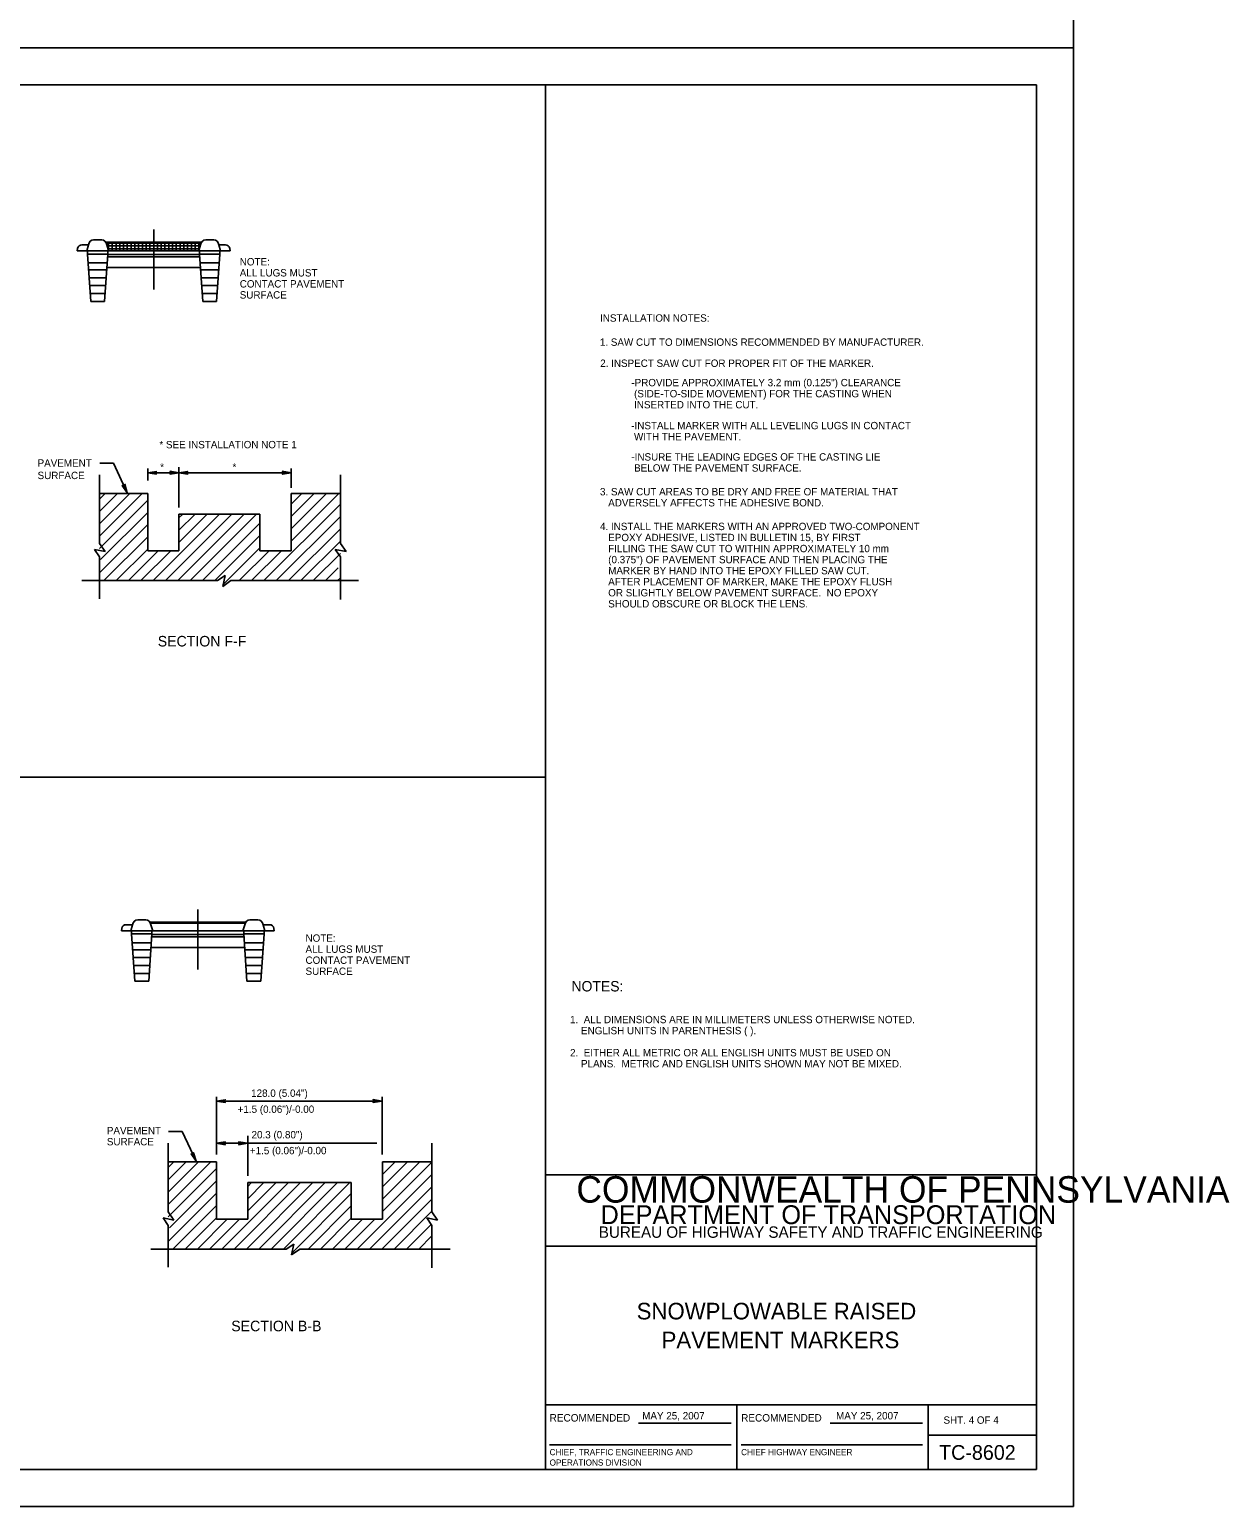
# Model space of a CAD drawing. Extents: x 639362 to 641108, y 298458 to 299646.
# Drawn here: x 640619 to 641108, y 298458 to 299059 of the extents above; entities that cross this region are included whole.
import ezdxf

# ---------------------------------------------------------------- set-up
doc = ezdxf.new("R2010")
doc.units = 0
for name, color, linetype in [('1', 7, 'Continuous'), ('2', 7, 'Continuous'), ('PLT-BNDY', 7, 'Continuous')]:
    doc.layers.add(name, color=color, linetype=linetype)

msp = doc.modelspace()

# ---------------------------------------------------------------- linework, layer by layer
at = {"layer": '1'}
for p, q in [((640243.31, 299036.63), (641029.31, 299036.63)), ((640829.31, 298592.63), (640829.31, 299036.63)), ((641029.31, 298472.63), (641029.31, 299036.63)), ((640243.31, 298754.63), (640829.31, 298754.63)), ((640829.31, 298472.63), (640829.31, 298592.63)), ((640829.31, 298592.63), (641029.31, 298592.63)), ((641029.31, 298563.63), (640829.31, 298563.63)), ((640829.31, 298499), (641029.31, 298499)), ((640907.31, 298499), (640907.31, 298472.63)), ((640985.19, 298472.63), (640985.19, 298499)), ((640867.24, 298491.57), (640904.87, 298491.57)), ((640945.24, 298491.57), (640982.87, 298491.57)), ((640830.99, 298482.68), (640904.87, 298482.68)), ((640908.99, 298482.68), (640982.87, 298482.68)), ((640985.19, 298486.63), (641029.31, 298486.63)), ((641029.31, 298472.63), (640243.31, 298472.63)), ((640243.31, 298472.63), (640829.31, 298472.63))]:
    msp.add_line(p, q, dxfattribs=at)
at = {"layer": '2'}
for p, q in [((640669.77, 298977.68), (640669.77, 298953.22)), ((640638.64, 298969.01), (640638.78, 298969.98)), ((640643.2, 298971.48), (640640.53, 298971.48)), ((640642.5, 298969.01), (640643.19, 298971.43)), ((640645.29, 298973.5), (640648.59, 298973.5)), ((640650.27, 298972.5), (640689.27, 298972.5)), ((640650.48, 298972.11), (640689.08, 298972.11)), ((640651.38, 298969.01), (640650.68, 298971.43)), ((640651.07, 298971.07), (640688.46, 298971.07)), ((640651.07, 298969.88), (640688.46, 298969.88)), ((640651.36, 298972.11), (640651.36, 298969.01)), ((640652.9, 298972.11), (640652.9, 298969.01)), ((640654.43, 298972.11), (640654.43, 298969.01)), ((640655.96, 298972.11), (640655.96, 298969.01)), ((640657.5, 298972.11), (640657.5, 298969.01)), ((640659.03, 298972.11), (640659.03, 298969.01)), ((640660.56, 298972.11), (640660.56, 298969.01)), ((640662.1, 298972.11), (640662.1, 298969.01)), ((640663.63, 298972.11), (640663.63, 298969.01)), ((640665.17, 298972.11), (640665.17, 298969.01)), ((640666.7, 298972.11), (640666.7, 298969.01)), ((640668.23, 298972.11), (640668.23, 298969.01)), ((640669.77, 298972.11), (640669.77, 298969.01)), ((640671.3, 298972.11), (640671.3, 298969.01)), ((640672.83, 298972.11), (640672.83, 298969.01)), ((640674.36, 298972.11), (640674.36, 298969.01)), ((640675.9, 298972.11), (640675.9, 298969.01)), ((640677.43, 298972.11), (640677.43, 298969.01)), ((640678.97, 298972.11), (640678.97, 298969.01)), ((640680.5, 298972.11), (640680.5, 298969.01)), ((640682.03, 298972.11), (640682.03, 298969.01)), ((640683.57, 298972.11), (640683.57, 298969.01)), ((640685.1, 298972.11), (640685.1, 298969.01)), ((640686.63, 298972.11), (640686.63, 298969.01)), ((640688.15, 298969.01), (640688.85, 298971.43)), ((640688.17, 298972.11), (640688.17, 298969.01)), ((640694.24, 298973.5), (640690.94, 298973.5)), ((640696.33, 298971.48), (640699, 298971.48)), ((640697.03, 298969.01), (640696.33, 298971.43)), ((640700.89, 298969.01), (640700.75, 298969.98)), ((640642.75, 298969.01), (640638.64, 298969.01)), ((640642.5, 298969.01), (640651.38, 298969.01)), ((640642.79, 298967.68), (640642.79, 298969.01)), ((640644.12, 298948.4), (640642.79, 298967.68)), ((640642.79, 298967.68), (640651.09, 298967.68)), ((640650.84, 298964.12), (640643.03, 298964.12)), ((640649.77, 298948.4), (640651.09, 298967.68)), ((640651.01, 298966.54), (640688.52, 298966.54)), ((640651.07, 298967.46), (640688.46, 298967.46)), ((640651.09, 298967.68), (640651.09, 298969.01)), ((640651.13, 298969.01), (640688.4, 298969.01)), ((640688.15, 298969.01), (640697.03, 298969.01)), ((640688.44, 298967.68), (640688.44, 298969.01)), ((640689.77, 298948.4), (640688.44, 298967.68)), ((640688.44, 298967.68), (640696.74, 298967.68)), ((640688.68, 298964.12), (640696.5, 298964.12)), ((640695.41, 298948.4), (640696.74, 298967.68)), ((640696.74, 298967.68), (640696.74, 298969.01)), ((640696.78, 298969.01), (640700.89, 298969.01)), ((640650.65, 298961.26), (640643.23, 298961.26)), ((640650.43, 298958.05), (640643.45, 298958.05)), ((640650.71, 298962.2), (640688.82, 298962.2)), ((640688.88, 298961.26), (640696.3, 298961.26)), ((640689.1, 298958.05), (640696.08, 298958.05)), ((640650.21, 298954.83), (640643.68, 298954.83)), ((640649.99, 298951.62), (640643.9, 298951.62)), ((640689.32, 298954.83), (640695.85, 298954.83)), ((640689.54, 298951.62), (640695.63, 298951.62)), ((640649.77, 298948.4), (640644.12, 298948.4)), ((640689.77, 298948.4), (640695.41, 298948.4)), ((640647.82, 298882.56), (640653.38, 298882.56)), ((640653.38, 298882.56), (640659, 298870.44)), ((640667.32, 298880.4), (640667.32, 298875.51)), ((640680.07, 298880.95), (640680.07, 298864.44)), ((640725.71, 298880.4), (640725.71, 298872.49)), ((640647.65, 298877.84), (640647.65, 298849.8)), ((640667.32, 298878.62), (640725.71, 298878.62)), ((640745.78, 298877.84), (640745.78, 298849.8)), ((640667.32, 298870.23), (640647.65, 298870.23)), ((640647.65, 298867.87), (640650.01, 298870.23)), ((640647.65, 298862.86), (640655.02, 298870.23)), ((640647.65, 298857.85), (640660.03, 298870.23)), ((640647.65, 298852.84), (640665.04, 298870.23)), ((640647.65, 298847.83), (640667.32, 298867.5)), ((640667.32, 298870.23), (640667.32, 298846.76)), ((640725.71, 298870.23), (640725.71, 298846.86)), ((640725.71, 298870.23), (640745.78, 298870.23)), ((640725.71, 298865.79), (640730.15, 298870.23)), ((640725.71, 298860.78), (640735.16, 298870.23)), ((640725.71, 298855.77), (640740.17, 298870.23)), ((640725.71, 298850.77), (640745.18, 298870.23)), ((640648.15, 298843.33), (640667.32, 298862.49)), ((640669.56, 298834.68), (640696.61, 298861.73)), ((640674.56, 298834.68), (640701.62, 298861.73)), ((640679.57, 298834.68), (640706.63, 298861.73)), ((640680.07, 298861.73), (640680.07, 298846.86)), ((640712.96, 298861.73), (640680.07, 298861.73)), ((640680.07, 298860.22), (640681.58, 298861.73)), ((640680.07, 298855.21), (640686.59, 298861.73)), ((640680.07, 298850.2), (640691.6, 298861.73)), ((640684.58, 298834.68), (640711.63, 298861.73)), ((640712.96, 298861.73), (640712.96, 298846.76)), ((640714.63, 298834.68), (640745.78, 298865.82)), ((640647.65, 298837.81), (640667.32, 298857.48)), ((640689.59, 298834.68), (640712.96, 298858.05)), ((640719.64, 298834.68), (640745.78, 298860.81)), ((640724.65, 298834.68), (640745.78, 298855.81)), ((640650, 298846.51), (640647.65, 298849.8)), ((640649.52, 298834.68), (640667.32, 298852.47)), ((640694.6, 298834.68), (640712.96, 298853.04)), ((640729.66, 298834.68), (640745.78, 298850.8)), ((640748.13, 298846.51), (640745.78, 298849.8)), ((640647.65, 298844.33), (640645.6, 298847.41)), ((640645.6, 298847.41), (640650, 298846.51)), ((640647.65, 298844.33), (640647.65, 298827.29)), ((640654.53, 298834.68), (640667.32, 298847.47)), ((640659.54, 298834.68), (640671.65, 298846.79)), ((640664.55, 298834.68), (640676.7, 298846.83)), ((640667.32, 298846.86), (640680.07, 298846.86)), ((640698.1, 298833.17), (640712.96, 298848.03)), ((640704.62, 298834.68), (640716.8, 298846.86)), ((640709.62, 298834.68), (640721.8, 298846.86)), ((640712.96, 298846.86), (640725.71, 298846.86)), ((640734.67, 298834.68), (640745.78, 298845.79)), ((640745.78, 298844.33), (640743.73, 298847.41)), ((640743.73, 298847.41), (640748.13, 298846.51)), ((640745.78, 298844.33), (640745.78, 298827.06)), ((640739.68, 298834.68), (640744.9, 298839.89)), ((640695.75, 298834.68), (640640.55, 298834.68)), ((640695.75, 298834.68), (640698.83, 298836.73)), ((640698.83, 298836.73), (640697.93, 298832.33)), ((640697.93, 298832.33), (640701.22, 298834.68)), ((640753.23, 298834.68), (640701.22, 298834.68)), ((640744.68, 298834.68), (640745.78, 298835.77)), ((640687.74, 298700.77), (640687.74, 298676.31)), ((640656.61, 298692.1), (640656.76, 298693.07)), ((640661.18, 298694.57), (640658.51, 298694.57)), ((640660.47, 298692.1), (640661.17, 298694.53)), ((640663.27, 298696.59), (640666.56, 298696.59)), ((640668.24, 298695.6), (640707.24, 298695.6)), ((640668.46, 298695.2), (640707.06, 298695.2)), ((640669.35, 298692.1), (640668.66, 298694.53)), ((640706.13, 298692.1), (640706.82, 298694.53)), ((640712.21, 298696.59), (640708.92, 298696.59)), ((640714.3, 298694.57), (640716.97, 298694.57)), ((640715, 298692.1), (640714.31, 298694.53)), ((640718.87, 298692.1), (640718.72, 298693.07)), ((640660.72, 298692.1), (640656.61, 298692.1)), ((640660.47, 298692.1), (640669.35, 298692.1)), ((640660.76, 298690.78), (640660.76, 298692.1)), ((640662.09, 298671.5), (640660.76, 298690.78)), ((640660.76, 298690.78), (640669.06, 298690.78)), ((640668.82, 298687.21), (640661.01, 298687.21)), ((640667.74, 298671.5), (640669.06, 298690.78)), ((640668.98, 298689.63), (640706.49, 298689.63)), ((640669.05, 298690.55), (640706.43, 298690.55)), ((640669.06, 298690.78), (640669.06, 298692.1)), ((640669.1, 298692.1), (640706.37, 298692.1)), ((640706.13, 298692.1), (640715, 298692.1)), ((640706.41, 298690.78), (640706.41, 298692.1)), ((640707.74, 298671.5), (640706.41, 298690.78)), ((640706.41, 298690.78), (640714.72, 298690.78)), ((640706.66, 298687.21), (640714.47, 298687.21)), ((640713.38, 298671.5), (640714.72, 298690.78)), ((640714.72, 298690.78), (640714.72, 298692.1)), ((640714.76, 298692.1), (640718.87, 298692.1)), ((640668.62, 298684.35), (640661.2, 298684.35)), ((640668.4, 298681.14), (640661.43, 298681.14)), ((640668.69, 298685.3), (640706.79, 298685.3)), ((640706.85, 298684.35), (640714.27, 298684.35)), ((640707.08, 298681.14), (640714.05, 298681.14)), ((640668.18, 298677.93), (640661.65, 298677.93)), ((640707.3, 298677.93), (640713.83, 298677.93)), ((640667.96, 298674.71), (640661.87, 298674.71)), ((640667.74, 298671.5), (640662.09, 298671.5)), ((640707.52, 298674.71), (640713.6, 298674.71)), ((640707.74, 298671.5), (640713.38, 298671.5)), ((640695.32, 298624.5), (640695.32, 298601)), ((640695.32, 298622.72), (640762.65, 298622.72)), ((640762.82, 298624.5), (640762.82, 298601)), ((640675.82, 298610.34), (640681.38, 298610.34)), ((640681.38, 298610.34), (640687.01, 298598.21)), ((640675.65, 298605.61), (640675.65, 298577.57)), ((640695.32, 298605.54), (640760.58, 298605.54)), ((640708.07, 298608.54), (640708.07, 298592.22)), ((640783.03, 298605.61), (640783.03, 298577.57)), ((640695.32, 298598), (640675.65, 298598)), ((640675.65, 298595.64), (640678.02, 298598)), ((640675.65, 298590.63), (640683.03, 298598)), ((640675.65, 298585.62), (640688.04, 298598)), ((640675.65, 298580.61), (640693.04, 298598)), ((640695.32, 298598), (640695.32, 298574.53)), ((640762.96, 298598), (640762.96, 298574.63)), ((640762.96, 298598), (640783.03, 298598)), ((640762.96, 298582.78), (640778.19, 298598)), ((640762.96, 298587.78), (640773.18, 298598)), ((640762.96, 298592.79), (640768.17, 298598)), ((640762.96, 298577.77), (640783.03, 298597.84)), ((640675.65, 298575.6), (640695.32, 298595.27)), ((640752.65, 298562.45), (640783.03, 298592.83)), ((640675.65, 298565.59), (640695.32, 298585.26)), ((640676.16, 298571.1), (640695.32, 298590.27)), ((640697.56, 298562.45), (640724.61, 298589.5)), ((640702.57, 298562.45), (640729.62, 298589.5)), ((640707.58, 298562.45), (640734.63, 298589.5)), ((640708.07, 298589.5), (640708.07, 298574.63)), ((640750.21, 298589.5), (640708.07, 298589.5)), ((640708.07, 298587.99), (640709.59, 298589.5)), ((640708.07, 298582.98), (640714.6, 298589.5)), ((640708.07, 298577.97), (640719.6, 298589.5)), ((640712.59, 298562.45), (640739.64, 298589.5)), ((640717.59, 298562.45), (640744.65, 298589.5)), ((640722.6, 298562.45), (640749.66, 298589.5)), ((640726.11, 298560.95), (640750.21, 298585.05)), ((640750.21, 298589.5), (640750.21, 298574.53)), ((640757.66, 298562.45), (640783.03, 298587.82)), ((640677.53, 298562.45), (640695.32, 298580.25)), ((640732.62, 298562.45), (640750.21, 298580.04)), ((640762.67, 298562.45), (640783.03, 298582.81)), ((640675.65, 298572.11), (640673.6, 298575.19)), ((640673.6, 298575.19), (640678, 298574.28)), ((640678, 298574.28), (640675.65, 298577.57)), ((640682.53, 298562.45), (640695.32, 298575.24)), ((640687.54, 298562.45), (640699.66, 298574.57)), ((640692.55, 298562.45), (640704.7, 298574.6)), ((640695.32, 298574.63), (640708.07, 298574.63)), ((640737.63, 298562.45), (640750.21, 298575.03)), ((640742.64, 298562.45), (640754.82, 298574.63)), ((640747.64, 298562.45), (640759.82, 298574.63)), ((640750.21, 298574.63), (640762.96, 298574.63)), ((640767.68, 298562.45), (640782.93, 298577.71)), ((640783.03, 298572.11), (640780.98, 298575.19)), ((640780.98, 298575.19), (640785.38, 298574.28)), ((640785.38, 298574.28), (640783.03, 298577.57)), ((640675.65, 298572.11), (640675.65, 298555.07)), ((640772.69, 298562.45), (640782.75, 298572.52)), ((640777.7, 298562.45), (640783.03, 298567.78)), ((640783.03, 298572.11), (640783.03, 298554.84)), ((640723.76, 298562.45), (640668.55, 298562.45)), ((640723.76, 298562.45), (640726.84, 298564.5)), ((640726.84, 298564.5), (640725.93, 298560.1)), ((640725.93, 298560.1), (640729.22, 298562.45)), ((640790.48, 298562.45), (640729.22, 298562.45))]:
    msp.add_line(p, q, dxfattribs=at)
for points in [[(640657.96, 298873.71), (640657.79, 298873.49), (640659, 298870.44), (640657.96, 298873.71), (640658.02, 298873.93), (640659, 298870.44), (640657.48, 298873.34), (640657.21, 298873.35), (640659, 298870.44), (640656.98, 298873.45), (640657.21, 298873.35)], [(640670.72, 298878.2), (640670.6, 298878.44), (640667.32, 298878.62), (640670.72, 298878.2), (640670.9, 298878.05), (640667.32, 298878.62), (640670.59, 298878.79), (640670.71, 298879.03), (640667.32, 298878.62), (640670.9, 298879.19), (640670.71, 298879.03)], [(640676.59, 298879.05), (640676.71, 298878.8), (640679.99, 298878.62), (640676.59, 298879.05), (640676.42, 298879.2), (640679.99, 298878.62), (640676.72, 298878.46), (640676.6, 298878.22), (640679.99, 298878.62), (640676.42, 298878.05), (640676.6, 298878.22)], [(640683.47, 298878.2), (640683.35, 298878.44), (640680.07, 298878.62), (640683.47, 298878.2), (640683.65, 298878.04), (640680.07, 298878.62), (640683.34, 298878.79), (640683.46, 298879.03), (640680.07, 298878.62), (640683.65, 298879.19), (640683.46, 298879.03)], [(640722.31, 298879.05), (640722.43, 298878.8), (640725.71, 298878.62), (640722.31, 298879.05), (640722.13, 298879.2), (640725.71, 298878.62), (640722.44, 298878.46), (640722.32, 298878.22), (640725.71, 298878.62), (640722.13, 298878.05), (640722.32, 298878.22)], [(640698.73, 298622.3), (640698.6, 298622.54), (640695.32, 298622.72), (640698.73, 298622.3), (640698.9, 298622.15), (640695.32, 298622.72), (640698.6, 298622.89), (640698.72, 298623.13), (640695.32, 298622.72), (640698.9, 298623.29), (640698.72, 298623.13)], [(640759.25, 298623.15), (640759.38, 298622.9), (640762.65, 298622.72), (640759.25, 298623.15), (640759.08, 298623.3), (640762.65, 298622.72), (640759.38, 298622.56), (640759.26, 298622.32), (640762.65, 298622.72), (640759.08, 298622.15), (640759.26, 298622.32)], [(640698.73, 298605.11), (640698.6, 298605.36), (640695.32, 298605.54), (640698.73, 298605.11), (640698.9, 298604.96), (640695.32, 298605.54), (640698.6, 298605.7), (640698.72, 298605.94), (640695.32, 298605.54), (640698.9, 298606.11), (640698.72, 298605.94)], [(640704.59, 298605.96), (640704.72, 298605.72), (640708, 298605.53), (640704.59, 298605.96), (640704.42, 298606.11), (640708, 298605.53), (640704.73, 298605.37), (640704.6, 298605.13), (640708, 298605.53), (640704.42, 298604.97), (640704.6, 298605.13)], [(640685.96, 298601.48), (640685.79, 298601.26), (640687.01, 298598.21), (640685.96, 298601.48), (640686.03, 298601.7), (640687.01, 298598.21), (640685.48, 298601.12), (640685.21, 298601.12), (640687.01, 298598.21), (640684.99, 298601.22), (640685.21, 298601.12)]]:
    msp.add_lwpolyline(points, dxfattribs=at)
for centre, start, end in [((640640.53, 298969.71), 90, 171.21944), ((640698.99, 298969.71), 8.78056, 90), ((640658.51, 298692.8), 90, 171.21944), ((640716.97, 298692.8), 8.78056, 90)]:
    msp.add_arc(centre, 1.77, start, end, dxfattribs=at)
for centre, start_param, end_param in [((640645.29, 298970.84), 0, 1.34621), ((640648.58, 298970.84), 4.937133, 6.283185), ((640690.94, 298970.84), 0, 1.346052), ((640694.24, 298970.84), 4.936975, 6.283185), ((640663.27, 298693.94), 0, 1.34621), ((640666.56, 298693.94), 4.937133, 6.283185), ((640708.92, 298693.94), 0, 1.346052), ((640712.21, 298693.94), 4.936975, 6.283185)]:
    msp.add_ellipse(centre, major_axis=(0, 2.66), ratio=0.81, start_param=start_param, end_param=end_param, dxfattribs=at)
at = {"layer": 'PLT-BNDY'}
for points in [[(640203.31, 299645.63), (641044.31, 299645.63), (641044.31, 299051.63), (640203.31, 299051.63)], [(640203.31, 299051.63), (641044.31, 299051.63), (641044.31, 298457.63), (640203.31, 298457.63)]]:
    msp.add_lwpolyline(points, close=True, dxfattribs=at)

# ---------------------------------------------------------------- texts
at = {"layer": '1'}
for s, height, p in [('COMMONWEALTH OF PENNSYLVANIA', 10.7828, (640841.9, 298581.36)), ('DEPARTMENT OF TRANSPORTATION', 7.6837, (640851.76, 298572.61)), ('BUREAU OF HIGHWAY SAFETY AND TRAFFIC ENGINEERING', 4.6253, (640851.04, 298567.04)), ('SNOWPLOWABLE RAISED', 6.75, (640866.46, 298533.81)), ('PAVEMENT MARKERS', 6.75, (640876.61, 298522.06)), ('RECOMMENDED', 3.048, (640830.99, 298492.2)), ('RECOMMENDED', 3.048, (640908.99, 298492.2)), ('SHT. 4 OF 4', 3, (640991.4, 298491.31)), ('TC-8602', 6, (640989.6, 298476.63)), ('OPERATIONS DIVISION', 2.5, (640830.99, 298474.26)), ('CHIEF, TRAFFIC ENGINEERING AND', 2.5, (640830.99, 298478.51)), ('CHIEF HIGHWAY ENGINEER', 2.5, (640908.99, 298478.51))]:
    msp.add_text(s, height=height, dxfattribs=at).set_placement(p)
at = {"layer": '2'}
for s, height, p in [('NOTE:', 3, (640704.81, 298963.06)), ('ALL LUGS MUST ', 3.0001, (640704.81, 298958.56)), ('SURFACE', 3, (640704.81, 298949.56)), ('CONTACT PAVEMENT', 3.0001, (640704.81, 298954.06)), ('INSTALLATION NOTES:', 3, (640851.54, 298940.15)), ('1. SAW CUT TO DIMENSIONS RECOMMENDED BY MANUFACTURER.', 3, (640851.46, 298930.32)), ('2. INSPECT SAW CUT FOR PROPER FIT OF THE MARKER.', 3, (640851.6, 298921.73)), ('-PROVIDE APPROXIMATELY 3.2 mm (0.125") CLEARANCE', 3, (640864.29, 298913.84)), (' (SIDE-TO-SIDE MOVEMENT) FOR THE CASTING WHEN', 3, (640864.29, 298909.34)), (' INSERTED INTO THE CUT.', 3, (640864.29, 298904.84)), ('-INSTALL MARKER WITH ALL LEVELING LUGS IN CONTACT', 3, (640864.25, 298896.33)), ('* SEE INSTALLATION NOTE 1', 3, (640672.08, 298888.58)), (' WITH THE PAVEMENT.', 3, (640864.25, 298891.83)), ('-INSURE THE LEADING EDGES OF THE CASTING LIE ', 3, (640864.3, 298883.58)), ('PAVEMENT', 3, (640622.48, 298881.09)), ('*', 3, (640672.42, 298879.45)), ('*', 3, (640701.87, 298879.45)), (' BELOW THE PAVEMENT SURFACE.', 3, (640864.3, 298879.08)), ('SURFACE', 3, (640622.48, 298876.03)), ('3. SAW CUT AREAS TO BE DRY AND FREE OF MATERIAL THAT', 3, (640851.52, 298869.4)), ('   ADVERSELY AFFECTS THE ADHESIVE BOND.', 3, (640851.52, 298864.9)), ('4. INSTALL THE MARKERS WITH AN APPROVED TWO-COMPONENT', 3, (640851.52, 298855.26)), ('   EPOXY ADHESIVE, LISTED IN BULLETIN 15, BY FIRST ', 3, (640851.52, 298850.76)), ('   FILLING THE SAW CUT TO WITHIN APPROXIMATELY 10 mm', 3, (640851.52, 298846.26)), ('   (0.375") OF PAVEMENT SURFACE AND THEN PLACING THE', 3, (640851.52, 298841.76)), ('   MARKER BY HAND INTO THE EPOXY FILLED SAW CUT.', 3, (640851.52, 298837.26)), ('   AFTER PLACEMENT OF MARKER, MAKE THE EPOXY FLUSH', 3, (640851.52, 298832.76)), ('   OR SLIGHTLY BELOW PAVEMENT SURFACE.  NO EPOXY', 3, (640851.52, 298828.26)), ('   SHOULD OBSCURE OR BLOCK THE LENS.', 3, (640851.52, 298823.76)), ('SECTION F-F', 4.3, (640671.41, 298807.87)), ('NOTE:', 3, (640731.6, 298687.61)), ('ALL LUGS MUST ', 3.0001, (640731.6, 298683.11)), ('CONTACT PAVEMENT', 3.0001, (640731.6, 298678.61)), ('SURFACE', 3, (640731.6, 298674.11)), ('NOTES:', 4.25, (640839.9, 298667.37)), ('1.  ALL DIMENSIONS ARE IN MILLIMETERS UNLESS OTHERWISE NOTED.', 3, (640839.33, 298654.44)), ('    ENGLISH UNITS IN PARENTHESIS ( ).', 3, (640839.33, 298649.94)), ('2.  EITHER ALL METRIC OR ALL ENGLISH UNITS MUST BE USED ON', 3, (640839.33, 298640.94)), ('    PLANS.  METRIC AND ENGLISH UNITS SHOWN MAY NOT BE MIXED.', 3, (640839.33, 298636.44)), ('128.0 (5.04")', 3, (640709.45, 298624.45)), ('+1.5 (0.06")/-0.00', 3, (640703.95, 298617.92)), ('PAVEMENT', 3, (640650.69, 298609.19)), ('20.3 (0.80")', 3, (640709.62, 298607.53)), ('SURFACE', 3, (640650.69, 298604.69)), ('+1.5 (0.06")/-0.00', 3, (640708.93, 298601.07)), ('SECTION B-B', 4.3, (640701.35, 298528.98)), ('MAY 25, 2007', 3, (640868.71, 298493.08)), ('MAY 25, 2007', 3, (640947.66, 298493.08))]:
    msp.add_text(s, height=height, dxfattribs=at).set_placement(p)

doc.saveas('drawing.dxf')
